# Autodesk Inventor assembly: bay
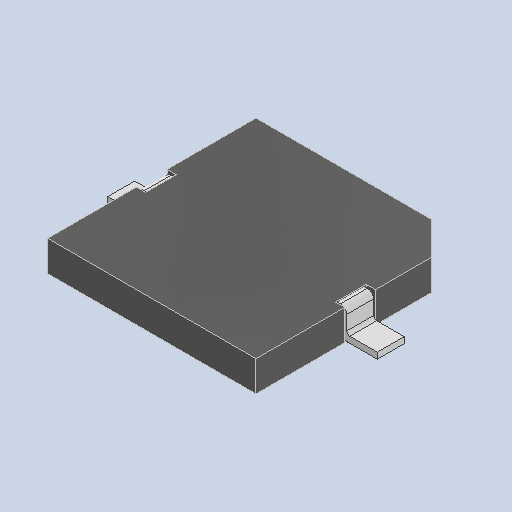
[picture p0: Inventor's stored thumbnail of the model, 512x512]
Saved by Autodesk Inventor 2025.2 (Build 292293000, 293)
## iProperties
Created: 2025-04
Part Number: bay
Description: PART--DESC
Document SubType Name: Assembly
Designer: BennF
Author: BennF
Revision Number: NONE
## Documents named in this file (3)
- C:\Users\BennF\Nextcloud\Benutzer\CNC JarBeRi\existing parts\Electronics\RepRap A4988 Shied (USE WITHOUT ARDUINO)\reprap-a4988-1.snapshot.1\RepRap\RepRap\bay_4.iam
- C:\Users\BennF\Nextcloud\Benutzer\CNC JarBeRi\existing parts\Electronics\RepRap A4988 Shied (USE WITHOUT ARDUINO)\reprap-a4988-1.snapshot.1\RepRap\RepRap\bay Geometry.ipt
- C:\Users\BennF\Nextcloud\Benutzer\CNC JarBeRi\existing parts\Electronics\RepRap A4988 Shied (USE WITHOUT ARDUINO)\reprap-a4988-1.snapshot.1\RepRap\RepRap\pin14.ipt
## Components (2 placed, 2 different names)
1. bay Geometry
2. pin14
